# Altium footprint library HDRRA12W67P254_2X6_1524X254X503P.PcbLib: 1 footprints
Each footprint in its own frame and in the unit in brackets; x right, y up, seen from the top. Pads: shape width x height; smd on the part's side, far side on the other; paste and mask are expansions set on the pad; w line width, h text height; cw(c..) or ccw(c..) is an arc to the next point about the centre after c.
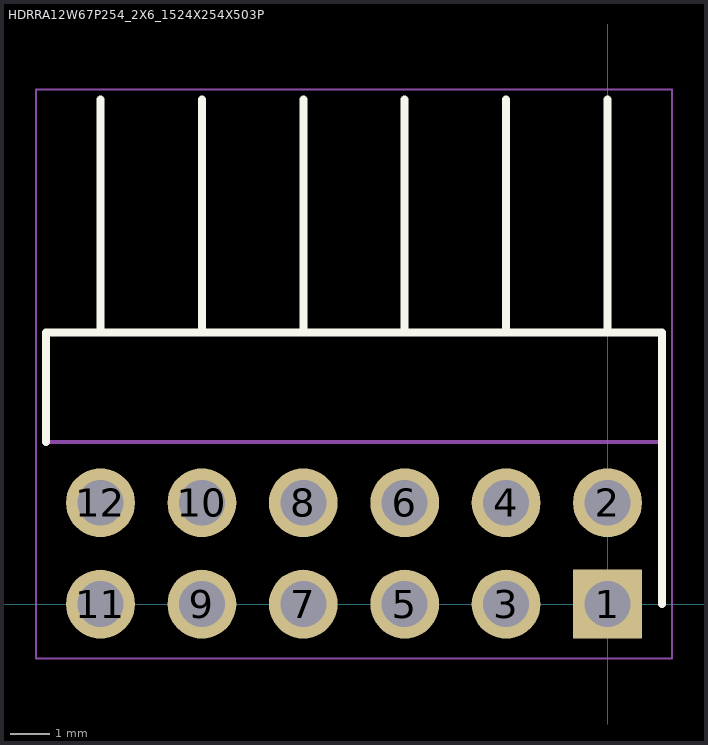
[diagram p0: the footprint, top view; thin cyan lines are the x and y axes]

## HDRRA12W67P254_2X6_1524X254X503P [mm]
pads (12):
  rect 1.725x1.725 / inner round 1.725 / far side rect 1.725x1.725 hole 1.15: 1(0,0)
  round 1.725 hole 1.15: 2(0,2.54) 3(-2.54,0) 4(-2.54,2.54) 5(-5.08,0) 6(-5.08,2.54) 7(-7.62,0) 8(-7.62,2.54) 9(-10.16,0) 10(-10.16,2.54) 11(-12.7,0) 12(-12.7,2.54)
Top Overlay:
  lines w0.2: -14.07,4.06 -14.07,6.8 1.37,6.8 1.37,0 ; -12.7,6.8 -12.7,12.64 ; -10.16,6.8 -10.16,12.64 ; -7.62,6.8 -7.62,12.64 ; -5.08,6.8 -5.08,12.64 ; -2.54,6.8 -2.54,12.64 ; 0,6.8 0,12.64
Mechanical 15:
  lines w0.1: -14.07,4.06 1.37,4.06 1.37,6.8 -14.07,6.8 -14.07,4.06
Mechanical 20:
  lines w0.05: -14.32,-1.362 1.62,-1.362 1.62,12.89 -14.32,12.89 -14.32,-1.362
